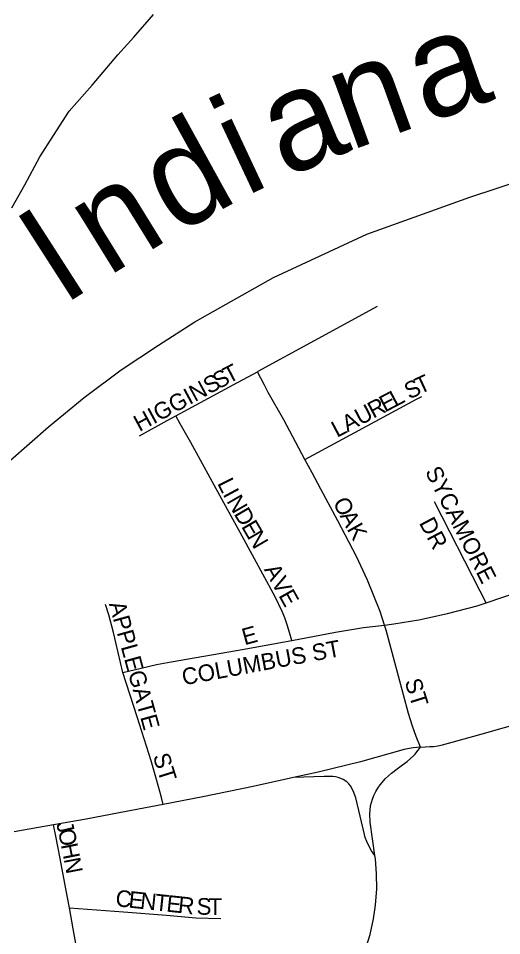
# Model space of a CAD drawing. Extents: x 1442749 to 1756758, y 235267 to 677782.
# Drawn here: x 1596851 to 1598304, y 529234 to 531991 of the extents above; entities that cross this region are included whole.
import ezdxf

# ---------------------------------------------------------------- set-up
doc = ezdxf.new("R2010")
doc.units = 0
for name, color, linetype in [('GM_X_City_Street', 7, 'Continuous'), ('GM_X_City_Street_Text', 7, 'Continuous'), ('GM_X_Interchange_Ramps', 7, 'Continuous'), ('GM_X_Minor_River', 7, 'Continuous'), ('GM_X_Rail_Line', 7, 'Continuous'), ('GM_X_Rail_Line_Text', 7, 'Continuous'), ('GM_X_US_Route', 7, 'Continuous')]:
    doc.layers.add(name, color=color, linetype=linetype)

msp = doc.modelspace()

# ---------------------------------------------------------------- linework, layer by layer
at = {"layer": 'GM_X_City_Street'}
for points in [[(1597569.6, 530929.5), (1597571.6, 530930.6), (1597741, 531023.3), (1597930.8, 531126.7)], [(1597323.7, 530796.3), (1597361.5, 530817), (1597496.6, 530890.4), (1597569.6, 530929.5)], [(1597712.2, 530665.6), (1597648.4, 530784.5), (1597601.8, 530867.3), (1597589.7, 530890.8), (1597569.6, 530929.5)], [(1597712.2, 530665.6), (1597738.2, 530679.6), (1597936.8, 530786.5), (1598046, 530845.7), (1598063.4, 530854.7)], [(1597215.4, 530736.3), (1597298.3, 530782.5), (1597323.7, 530796.3)], [(1597673.2, 530121.9), (1597666, 530146), (1597659.3, 530168.3), (1597651.5, 530189.4), (1597643.8, 530208.5), (1597622.4, 530253), (1597524, 530434.8), (1597462.4, 530546.8), (1597369.5, 530716.3), (1597336.9, 530773.2), (1597323.7, 530796.3)], [(1597951.8, 530168), (1597938.6, 530208.7), (1597900.5, 530302.6), (1597867.1, 530373.7), (1597811.4, 530481.4), (1597759.6, 530576.3), (1597733.6, 530625.5), (1597712.2, 530665.6)], [(1598257, 530235.1), (1598239.3, 530269.7), (1598102.1, 530538.7)], [(1598257, 530235.1), (1598357.7, 530268.3)], [(1597164.8, 530025.4), (1597136.9, 530145.7), (1597122.4, 530198.6), (1597112.3, 530229.9)], [(1597951.8, 530168), (1597979.8, 530171.4), (1598054.3, 530183.8), (1598141, 530202.3), (1598229.8, 530226.1), (1598257, 530235.1)], [(1597673.2, 530121.9), (1597804.4, 530146.3), (1597888.5, 530160.5), (1597951.8, 530168)], [(1598060.1, 529801.2), (1598046.6, 529832.8), (1598035.5, 529863.9), (1598023.6, 529902.5), (1597979, 530070.6), (1597956.7, 530152.8), (1597951.8, 530168)], [(1597164.8, 530025.4), (1597220.1, 530038.8), (1597266.2, 530049.3), (1597310.1, 530057.4), (1597530, 530095.1), (1597601, 530108.5), (1597673.2, 530121.9)], [(1597286.3, 529628.9), (1597280.9, 529649.3), (1597266.5, 529703.3), (1597249.5, 529759.8), (1597208.1, 529891.7), (1597164.8, 530025.4)], [(1597004, 529318), (1596993.1, 529375), (1596976.2, 529466.2), (1596963.1, 529533.8), (1596956.6, 529567.3)], [(1597004, 529318), (1597167.3, 529306.3), (1597296.2, 529295.9), (1597384.3, 529288.1), (1597459.6, 529285.7)], [(1597051, 529054), (1597042.9, 529106.1), (1597037, 529138.8), (1597015.6, 529254.7), (1597004, 529318)]]:
    msp.add_lwpolyline(points, dxfattribs=at)
at = {"layer": 'GM_X_Interchange_Ramps'}
msp.add_lwpolyline([(1597922.7, 529475.4), (1597912.8, 529489.3), (1597902.9, 529506.5), (1597898, 529517.1), (1597893.5, 529529.8), (1597891.6, 529538.2), (1597865.4, 529648.6), (1597857.3, 529670.1), (1597849.1, 529684.3), (1597844.1, 529690.5), (1597838, 529696.4), (1597827.1, 529703.8), (1597820.3, 529707.1), (1597811.9, 529709.9), (1597804.2, 529711.7), (1597795.7, 529712.7), (1597770.2, 529713), (1597677.6, 529709.5)], dxfattribs=at)
at = {"layer": 'GM_X_Minor_River'}
msp.add_lwpolyline([(1596831.4, 531421.8), (1596870.3, 531491.5), (1596915.4, 531575.3), (1596956.2, 531639), (1597003.2, 531712.7), (1597072.3, 531790.1), (1597149.5, 531881.5), (1597198.2, 531935.1), (1597257.2, 532002.6)], dxfattribs=at)
at = {"layer": 'GM_X_Rail_Line'}
msp.add_lwpolyline([(1595210.5, 529107.4), (1595425.3, 529288.6), (1595598.8, 529439.7), (1595811.4, 529643.4), (1596016.1, 529852.6), (1596172.8, 530013.7), (1596308.2, 530154.7), (1596427.9, 530278.9), (1596586.8, 530434.4), (1596708.7, 530549.7), (1596827.4, 530663.8), (1596941.5, 530763.4), (1597048.9, 530851.8), (1597159.7, 530934.6), (1597271.6, 531009.6), (1597381.2, 531079), (1597617.9, 531213), (1597898, 531342.7), (1598208.1, 531454), (1598609.8, 531586.5)], dxfattribs=at)
at = {"layer": 'GM_X_US_Route'}
for points in [[(1598060.1, 529801.2), (1598073.5, 529802), (1598087.5, 529802.5), (1598099, 529803.3), (1598112.2, 529805.4), (1598125.5, 529808.1), (1598237.7, 529838.9), (1598563, 529931.2), (1598717.6, 529975.8), (1598795.7, 529998.4), (1598940.8, 530039), (1598976.9, 530049.2), (1599149.1, 530097.9), (1599260.6, 530129.3), (1599307.9, 530142.5), (1599333.3, 530149.7)], [(1598060.1, 529801.2), (1598038, 529799.4), (1598020.7, 529795.9), (1598010.1, 529793.6), (1597879.4, 529757), (1597751.8, 529725.7), (1597677.6, 529709.5), (1597556.3, 529683), (1597405.3, 529651.8), (1597286.3, 529628.9), (1597154.2, 529603.4), (1597054.3, 529584.4), (1596956.6, 529567.3), (1596837.9, 529546.6)], [(1597892.4, 529187.3), (1597908, 529237.6), (1597918.7, 529284.9), (1597924.8, 529326.4), (1597928, 529374.8), (1597927.8, 529420), (1597924.2, 529465.1), (1597922.7, 529475.4), (1597908, 529575.9), (1597907.1, 529600), (1597909.8, 529624.4), (1597915.2, 529644.8), (1597919.6, 529655.6), (1597925.1, 529667.3), (1597931.5, 529677.7), (1597938.3, 529687.9), (1597954.2, 529706.4), (1597972.2, 529722.5), (1597989.3, 529735.7), (1598005.8, 529747.9), (1598020, 529758.1), (1598039.4, 529775.4), (1598044, 529780.3), (1598049, 529786.7), (1598060.1, 529801.2)]]:
    msp.add_lwpolyline(points, dxfattribs=at)

# ---------------------------------------------------------------- texts
at = {"layer": 'GM_X_City_Street_Text'}
for s, rotation, p in [('T', 27.5549, (1597482.7, 530892.2)), ('HIGGINS', 28.3625, (1597214.6, 530747.8)), ('S', 28.7892, (1597452.1, 530875.3)), ('T', 24.8782, (1598057.7, 530860.7)), ('S', 26.3818, (1598026.4, 530845.2)), ('E', 27.8241, (1597952.7, 530806.3)), ('L', 27.8635, (1597983.9, 530822.7)), ('U', 27.8359, (1597878.8, 530767.3)), ('R', 27.7925, (1597917.7, 530787.8)), ('A', 27.8359, (1597839.9, 530746.7)), ('L', 27.8476, (1597808.7, 530730.3)), ('SYCAMORE', 296.8961, (1598072.3, 530629.4)), ('L', 296.8338, (1597447.6, 530594.1)), ('I', 298.4077, (1597464.2, 530561.4)), ('N', 299.9473, (1597475.3, 530540.7)), ('O', 296.7019, (1597795.2, 530536.9)), ('D', 300.244, (1597497.4, 530502.4)), ('A', 298.3849, (1597815.7, 530496.2)), ('E', 300.2328, (1597519.6, 530464.4)), ('K', 299.3272, (1597837, 530456.7)), ('DR', 297.8967, (1598054.3, 530475.3)), ('N', 300.244, (1597537.3, 530434)), ('AVE', 299.2547, (1597588.1, 530334.9)), ('APPLEGATE', 285.4473, (1597122.6, 530231.9)), ('E', 15.2776, (1597530.6, 530107)), ('COLUMBUS ST', 10.5116, (1597347.3, 529986.6)), ('ST', 287.3587, (1598011.3, 529998.8)), ('ST', 287.3587, (1597254.5, 529774.4)), ('J', 283.4006, (1596964.2, 529571.6)), ('O', 282.0856, (1596969.3, 529550.4)), ('H', 281.0655, (1596978.4, 529507.6)), ('N', 280.8855, (1596986.9, 529464.5)), ('C', 353.9173, (1597141, 529323.3)), ('E', 353.9178, (1597180.3, 529319.1)), ('N', 353.9132, (1597215.3, 529315.4)), ('T', 353.9032, (1597259.1, 529310.7)), ('E', 353.9223, (1597294.1, 529307)), ('R', 353.9068, (1597329.1, 529303.3)), ('S', 358.5995, (1597386.1, 529297.9)), ('T', 359.8823, (1597422.5, 529297))]:
    msp.add_text(s, height=50, rotation=rotation, dxfattribs=at).set_placement(p)
at = {"layer": 'GM_X_Rail_Line_Text'}
for s, rotation, p in [('a', 19.3109, (1598077.4, 531676.1)), ('n', 19.9298, (1597846.9, 531592.5)), ('i', 25.1051, (1597533.1, 531455.5)), ('a', 22.5801, (1597652.4, 531511.5)), ('d', 28.8715, (1597323.5, 531339.7)), ('n', 31.7195, (1597118.5, 531212.8)), ('I', 32.743, (1596983.2, 531125.8))]:
    msp.add_text(s, height=299, rotation=rotation, dxfattribs=at).set_placement(p)

doc.saveas('drawing.dxf')
